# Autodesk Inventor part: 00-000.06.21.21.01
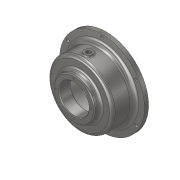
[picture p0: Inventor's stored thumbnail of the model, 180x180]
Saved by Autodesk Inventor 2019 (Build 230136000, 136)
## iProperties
Created: 2019-01
Part Number: 00-000.06.21.21.01
Material: Steel, Mild
Document SubType Name: Modeling
Designer: m.vorobev
Density: 7.85 g/cm^3
Appearance: Semi-Polished
Author: m.vorobev
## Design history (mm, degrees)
sketch "Sketch1"
  geometry: L1 (145, 0)-(100, 0); L2 (100, 0)-(100, 14); L3 (100, 14)-(145, 14); L4 (145, 14)-(145, 0); L5 (100, 14)-(110, 14); L6 (110, 14)-(110, 41); L7 (110, 41)-(100, 41); L8 (100, 41)-(100, 14); L9 (110, 41)-(100, 41); L10 (100, 41)-(100, 89); L11 (100, 89)-(110, 89); L12 (110, 89)-(110, 41); L13 (100, 89)-(70, 89); L14 (70, 89)-(70, 71); L15 (70, 71)-(100, 71); L16 (100, 71)-(100, 89); L17 (50, 70)-(70, 70); L18 (70, 70)-(70, 110); L19 (70, 110)-(50, 110); L20 (50, 110)-(50, 70); L21 (0, 0)-(19.228, 0); L22 (0, 36.823)-(0, 0); L23 (100, 0)-(125, 0); L24 (125, 0)-(125, 4); L25 (125, 4)-(100, 4); L26 (100, 4)-(100, 0); 1 further point
  constraints: 52 end point, 12 parallel, 7 horizontal, 6 perpendicular, 2 collinear, 1 horizontal alignment, 1 midpoint
  dimensions: "d0" = 290 diameter of L4 L22; "d1" = 220 diameter of L12 L22; "d2" = 140 diameter of L18 L22; "d3" = 200 diameter of L10 L22; "d4" = 14 distance of L3.end L1.start; "d5" = 75 distance between parallel lines of L13 L3; "d6" = 18 distance of L13.end L14.end; "d7" = 40 distance of L19.end L17.start; "d8" = 100 diameter of L20 L22; "d9" = 110 distance between parallel lines of L1 L19; "d11" = 4 distance of L23.end L24.end; "d12" = 250 diameter of L24.end L22
revolve "Revolution1" sketch "Sketch1" stored, may be unused: angle "d16" = 90 deg
fillet "Fillet1" dims "d17" = 10, "d18" = 15, "d19" = 3
chamfer "Chamfer1" distance "d20" = 3; stored, may be unused: second distance "d21" = 2, angle "d22" = 45 deg
chamfer "Chamfer2" distance "d23" = 2.5; stored, may be unused: second distance "d24" = 2, angle "d25" = 45 deg
sketch "Sketch2"
  geometry: L1 (43.589, 90)-(-43.589, 90); L2 (-43.589, 90)-(-43.589, 101.006); L3 (-43.589, 101.006)-(43.589, 101.006); L4 (43.589, 101.006)-(43.589, 90); A1 r 100 centre (0, 0) between (43.589, 90) and (-43.589, 90) reference; 1 further point
  constraints: 8 end point, 2 parallel, 2 point on circle, 1 horizontal, 1 perpendicular
  dimensions: "d27" = 90 distance from line of point (0, 0) L1
extrude "Extrusion1" join sketch "Sketch2" distance "d28" = 22; taper "d29" = 0 deg
sketch "Sketch3"
  geometry: L1 (0, 0)-(87.178, 0) reference; 2 further points
  constraints: 1 midpoint
hole "Hole1" sketch "Sketch3" at (43.589, 0) diameter "d30" = 20; stored, may be unused: countersink angle "d34" = 90 deg, drill point angle "d36" = 118 deg; dims "d31" = 6, "d32" = 4, "d33" = 2, "d35" = 25
chamfer "Chamfer3" distance "d37" = 1; stored, may be unused: second distance "d38" = 2, angle "d39" = 45 deg
pattern_circular "Circular Pattern1" dims angle "d41" = 360 deg
sketch "Sketch4"
  geometry: L1 (104.836, 60)-(115, 60); L2 (115, 60)-(115, 46); L3 (115, 46)-(104.836, 46); L4 (104.836, 46)-(104.836, 60); L5 (125, 0)-(-125, 0) reference; 1 further point
  constraints: 8 end point, 2 parallel, 1 horizontal, 1 perpendicular
  dimensions: "d43" = 60 distance from line of L5 L1.end; "d44" = 28 diameter of L3 L1; "d45" = 115 distance from line of point (0, 0) L2
revolve "Revolution2" sketch "Sketch4" stored, may be unused: angle "d46" = 90 deg
sketch "Sketch5"
  geometry: C1 r 14 at (0, 0) reference; 2 further points
  constraints: 1 coincident
hole "Hole2" sketch "Sketch5" at (0, 0) diameter "d47" = 13.835; stored, may be unused: countersink angle "d51" = 90 deg, drill point angle "d53" = 118 deg; dims "d48" = 32, "d49" = 16, "d50" = 2, "d52" = 41.3
fillet "Fillet2" dims "d54" = 3
pattern_circular "Circular Pattern2" dims angle "d56" = 360 deg
sketch "Sketch6"
  geometry: L1 (0, 0)-(0, -60)
  constraints: 2 end point, 1 vertical
  dimensions: "d58" = 60 distance of L1.start L1.end
hole "Hole3" sketch "Sketch6" at (0, -60) diameter "d59" = 6.647; stored, may be unused: countersink angle "d63" = 90 deg, drill point angle "d65" = 118 deg; dims "d60" = 59.25, "d61" = 16, "d62" = 2, "d64" = 100.7
pattern_circular "Circular Pattern3" dims angle "d67" = 360 deg
sketch "Sketch7"
  geometry: L1 (0, 0)-(0, 135)
  constraints: 2 end point, 1 vertical
  dimensions: "d69" = 135 distance of L1.start L1.end
hole "Hole4" sketch "Sketch7" at (0, 135) diameter "d70" = 11; stored, may be unused: countersink angle "d74" = 90 deg, drill point angle "d76" = 118 deg; dims "d71" = 59.25, "d72" = 16, "d73" = 2, "d75" = 100.7
pattern_circular "Circular Pattern4" dims angle "d78" = 360 deg
sketch "Sketch8"
  geometry: L1 (87.178, 0)-(-5.485, 0); L2 (-5.485, 0)-(-5.485, -67.713); L3 (-5.485, -67.713)-(87.178, -67.713); L4 (87.178, -67.713)-(87.178, 0); C1 r 25 at (43.589, -26); 1 further point
  constraints: 8 end point, 2 parallel, 1 centre point, 1 coincident, 1 horizontal, 1 perpendicular
  dimensions: "d80" = 50 diameter of C1
extrude "Extrusion2" cut sketch "Sketch8" stored distance "d81" = 20; taper "d82" = 0 deg
pattern_circular "Circular Pattern5" dims angle "d84" = 360 deg
delete_face "Delete Face1"
delete_face "Delete Face2"
delete_face "Delete Face3"
delete_face "Delete Face4"
body "Solid1"
